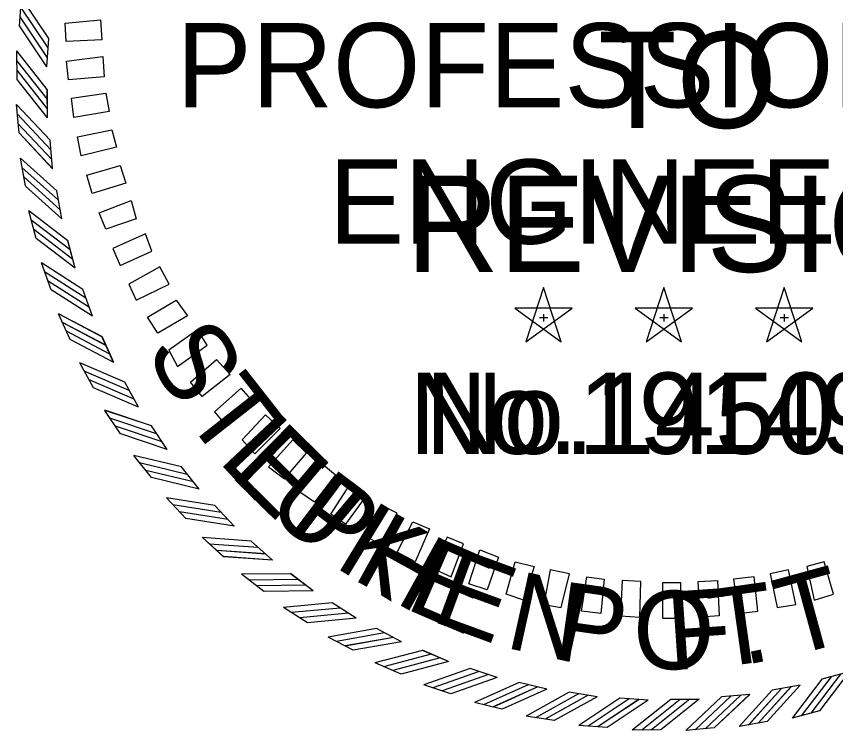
# Model space of a CAD drawing. Extents: x 16 to 1228740, y 11 to 152440.
# Drawn here: x 17.6793 to 17.7882, y 10.8149 to 10.9098 of the extents above; entities that cross this region are included whole.
import ezdxf

# ---------------------------------------------------------------- set-up
doc = ezdxf.new("R2010")
doc.units = 0
for name, color, linetype in [('STAMP_FRED', 7, 'Continuous'), ('STAMP_LUKE', 7, 'Continuous'), ('STAMP_PRELIM', 7, 'Continuous')]:
    doc.layers.add(name, color=color, linetype=linetype)

msp = doc.modelspace()

# ---------------------------------------------------------------- linework, layer by layer
at = {"layer": 'STAMP_FRED'}
for p, q in [((17.6797, 10.90852), (17.67998, 10.91228)), ((17.68332, 10.9031), (17.6836, 10.90687)), ((17.67937, 10.90143), (17.67934, 10.9052)), ((17.68343, 10.89632), (17.68339, 10.9001)), ((17.67963, 10.89432), (17.67928, 10.89808)), ((17.68409, 10.88957), (17.68375, 10.89333)), ((17.68047, 10.88727), (17.67982, 10.89098)), ((17.68531, 10.8829), (17.68466, 10.88662)), ((17.68189, 10.8803), (17.68093, 10.88395)), ((17.68708, 10.87635), (17.68612, 10.88)), ((17.68389, 10.87348), (17.68263, 10.87704)), ((17.68938, 10.86997), (17.68812, 10.87353)), ((17.74935, 10.87379), (17.747, 10.86655)), ((17.7517, 10.86656), (17.74936, 10.8738)), ((17.76534, 10.87379), (17.76299, 10.86655)), ((17.76769, 10.86656), (17.76535, 10.8738)), ((17.78134, 10.87379), (17.77898, 10.86655)), ((17.78369, 10.86656), (17.78134, 10.8738)), ((17.75316, 10.87103), (17.74555, 10.87103)), ((17.74555, 10.87103), (17.7517, 10.86655)), ((17.747, 10.86656), (17.75317, 10.87102)), ((17.76915, 10.87103), (17.76154, 10.87103)), ((17.76154, 10.87103), (17.7677, 10.86655)), ((17.763, 10.86656), (17.76916, 10.87102)), ((17.78514, 10.87103), (17.77753, 10.87103)), ((17.77753, 10.87103), (17.78369, 10.86655)), ((17.77899, 10.86656), (17.78515, 10.87102)), ((17.68644, 10.86685), (17.68489, 10.87029)), ((17.74881, 10.86981), (17.74994, 10.86981)), ((17.74936, 10.87022), (17.74936, 10.86926)), ((17.7648, 10.86981), (17.76593, 10.86981)), ((17.76535, 10.87022), (17.76535, 10.86926)), ((17.78079, 10.86981), (17.78193, 10.86981)), ((17.78134, 10.87022), (17.78134, 10.86926)), ((17.6922, 10.8638), (17.69065, 10.86725)), ((17.68952, 10.86045), (17.6877, 10.86375)), ((17.69552, 10.85789), (17.6937, 10.8612)), ((17.69313, 10.85433), (17.69104, 10.85746)), ((17.69932, 10.85227), (17.69723, 10.85541)), ((17.69723, 10.84852), (17.69489, 10.85148)), ((17.70357, 10.84698), (17.70122, 10.84994)), ((17.7018, 10.84308), (17.69922, 10.84583)), ((17.70824, 10.84207), (17.70566, 10.84482)), ((17.7068, 10.83802), (17.704, 10.84055)), ((17.7133, 10.83755), (17.7105, 10.84009)), ((17.71219, 10.8334), (17.7092, 10.83569)), ((17.71872, 10.83347), (17.71571, 10.83576)), ((17.72445, 10.82985), (17.72127, 10.83189)), ((17.71796, 10.82925), (17.71478, 10.83128)), ((17.73047, 10.82672), (17.72713, 10.82848)), ((17.72404, 10.82558), (17.72071, 10.82734)), ((17.73672, 10.82409), (17.73325, 10.82557)), ((17.73041, 10.82242), (17.72695, 10.82391)), ((17.74317, 10.82199), (17.73958, 10.82318)), ((17.78999, 10.82272), (17.78633, 10.82176)), ((17.73702, 10.81981), (17.73344, 10.821)), ((17.74977, 10.82042), (17.7461, 10.82132)), ((17.78344, 10.82095), (17.77972, 10.82029)), ((17.75647, 10.81941), (17.75274, 10.82)), ((17.77677, 10.81973), (17.77301, 10.81938)), ((17.74382, 10.81774), (17.74016, 10.81864)), ((17.76324, 10.81896), (17.75947, 10.81924)), ((17.77002, 10.81906), (17.76624, 10.81903)), ((17.78603, 10.81753), (17.78239, 10.81657)), ((17.75077, 10.81625), (17.74704, 10.81684)), ((17.75781, 10.81533), (17.75405, 10.81561)), ((17.77202, 10.81526), (17.76826, 10.81492)), ((17.77907, 10.81611), (17.77536, 10.81545)), ((17.76491, 10.815), (17.76114, 10.81497))]:
    msp.add_line(p, q, dxfattribs=at)
for points in [[(17.6836, 10.90686), (17.67997, 10.91229)], [(17.68349, 10.90561), (17.67987, 10.91104)], [(17.68343, 10.9043), (17.6798, 10.90973)], [(17.68333, 10.90309), (17.6797, 10.90852)], [(17.68339, 10.90009), (17.67933, 10.9052)], [(17.68339, 10.89884), (17.67933, 10.90394)], [(17.68343, 10.89753), (17.67937, 10.90263)], [(17.68343, 10.89631), (17.67937, 10.90142)], [(17.68375, 10.89333), (17.67928, 10.89808)], [(17.68385, 10.89208), (17.67938, 10.89683)], [(17.684, 10.89077), (17.67953, 10.89553)], [(17.6841, 10.88956), (17.67963, 10.89432)], [(17.68466, 10.88661), (17.67981, 10.89098)], [(17.68486, 10.88538), (17.68002, 10.88974)], [(17.68512, 10.88409), (17.68028, 10.88846)], [(17.68532, 10.88289), (17.68047, 10.88726)], [(17.68612, 10.88), (17.68093, 10.88395)], [(17.68643, 10.87878), (17.68124, 10.88274)], [(17.68679, 10.87752), (17.6816, 10.88148)], [(17.68709, 10.87635), (17.6819, 10.8803)], [(17.68812, 10.87353), (17.68263, 10.87704)], [(17.68853, 10.87234), (17.68303, 10.87585)], [(17.68899, 10.87112), (17.6835, 10.87463)], [(17.68939, 10.86997), (17.68389, 10.87348)], [(17.69065, 10.86724), (17.68489, 10.87029)], [(17.69116, 10.86609), (17.68539, 10.86914)], [(17.69172, 10.86491), (17.68595, 10.86796)], [(17.69221, 10.8638), (17.68644, 10.86685)], [(17.6937, 10.86119), (17.6877, 10.86375)], [(17.69429, 10.86009), (17.68829, 10.86265)], [(17.69495, 10.85895), (17.68895, 10.86151)], [(17.69553, 10.85789), (17.68953, 10.86045)], [(17.69723, 10.85541), (17.69104, 10.85746)], [(17.69791, 10.85436), (17.69172, 10.85641)], [(17.69866, 10.85328), (17.69247, 10.85534)], [(17.69933, 10.85227), (17.69314, 10.85432)], [(17.70122, 10.84994), (17.69488, 10.85148)], [(17.70199, 10.84895), (17.69566, 10.85049)], [(17.70283, 10.84794), (17.69649, 10.84948)], [(17.70358, 10.84698), (17.69724, 10.84852)], [(17.70566, 10.84482), (17.69921, 10.84583)], [(17.70651, 10.84389), (17.70006, 10.8449)], [(17.70743, 10.84296), (17.70098, 10.84397)], [(17.70825, 10.84207), (17.7018, 10.84307)], [(17.7105, 10.84008), (17.70399, 10.84055)], [(17.71142, 10.83923), (17.70492, 10.8397)], [(17.71241, 10.83837), (17.70591, 10.83885)], [(17.71331, 10.83755), (17.7068, 10.83802)], [(17.71572, 10.83576), (17.70919, 10.83569)], [(17.71671, 10.83499), (17.71019, 10.83492)], [(17.71777, 10.83422), (17.71124, 10.83415)], [(17.71872, 10.83347), (17.7122, 10.8334)], [(17.72127, 10.83188), (17.71478, 10.83128)], [(17.72232, 10.8312), (17.71583, 10.83059)], [(17.72344, 10.83051), (17.71695, 10.82991)], [(17.72446, 10.82985), (17.71796, 10.82925)], [(17.72713, 10.82848), (17.72071, 10.82734)], [(17.72823, 10.82788), (17.72181, 10.82674)], [(17.72941, 10.82729), (17.72298, 10.82615)], [(17.73047, 10.82672), (17.72405, 10.82558)], [(17.73325, 10.82557), (17.72694, 10.8239)], [(17.7344, 10.82507), (17.72809, 10.8234)], [(17.73561, 10.82458), (17.72931, 10.82291)], [(17.73673, 10.82409), (17.73042, 10.82242)], [(17.73959, 10.82318), (17.73344, 10.821)], [(17.74077, 10.82277), (17.73463, 10.82059)], [(17.74203, 10.82238), (17.73588, 10.8202)], [(17.74317, 10.82199), (17.73703, 10.81981)], [(17.78634, 10.82175), (17.78239, 10.81657)], [(17.78756, 10.82206), (17.7836, 10.81687)], [(17.78882, 10.82242), (17.78486, 10.81723)], [(17.78999, 10.82272), (17.78604, 10.81753)], [(17.7461, 10.82131), (17.74015, 10.81863)], [(17.74732, 10.82101), (17.74137, 10.81833)], [(17.7486, 10.82072), (17.74265, 10.81804)], [(17.78225, 10.82075), (17.77788, 10.81591)], [(17.78345, 10.82095), (17.77908, 10.81611)], [(17.74977, 10.82043), (17.74383, 10.81775)], [(17.75274, 10.82), (17.74704, 10.81683)], [(17.75398, 10.81979), (17.74828, 10.81663)], [(17.75528, 10.81961), (17.74958, 10.81645)], [(17.77556, 10.81963), (17.77081, 10.81517)], [(17.77677, 10.81973), (17.77202, 10.81527)], [(17.77972, 10.82029), (17.77536, 10.81545)], [(17.78096, 10.8205), (17.77659, 10.81565)], [(17.75648, 10.81942), (17.75077, 10.81625)], [(17.75948, 10.81923), (17.75405, 10.81561)], [(17.76073, 10.81913), (17.7553, 10.81551)], [(17.76204, 10.81906), (17.75661, 10.81544)], [(17.76324, 10.81896), (17.75782, 10.81534)], [(17.76625, 10.81903), (17.76114, 10.81497)], [(17.7675, 10.81903), (17.7624, 10.81497)], [(17.76881, 10.81907), (17.76371, 10.81501)], [(17.77003, 10.81907), (17.76492, 10.81501)], [(17.77301, 10.81938), (17.76826, 10.81491)], [(17.77426, 10.81948), (17.76951, 10.81502)]]:
    msp.add_lwpolyline(points, dxfattribs=at)
at = {"layer": 'STAMP_LUKE'}
for p, q in [((17.6797, 10.90852), (17.67998, 10.91228)), ((17.68332, 10.9031), (17.6836, 10.90687)), ((17.67937, 10.90143), (17.67934, 10.9052)), ((17.68343, 10.89632), (17.6834, 10.9001)), ((17.67963, 10.89432), (17.67928, 10.89808)), ((17.6841, 10.88957), (17.68375, 10.89333)), ((17.68047, 10.88727), (17.67982, 10.89098)), ((17.68532, 10.8829), (17.68466, 10.88662)), ((17.68189, 10.88031), (17.68094, 10.88395)), ((17.68708, 10.87635), (17.68612, 10.88001)), ((17.68389, 10.87348), (17.68263, 10.87704)), ((17.68938, 10.86997), (17.68812, 10.87353)), ((17.74935, 10.87379), (17.74699, 10.86655)), ((17.7517, 10.86656), (17.74936, 10.8738)), ((17.76534, 10.87379), (17.76299, 10.86655)), ((17.76769, 10.86656), (17.76535, 10.8738)), ((17.78133, 10.87379), (17.77898, 10.86655)), ((17.78368, 10.86656), (17.78134, 10.8738)), ((17.75316, 10.87103), (17.74554, 10.87103)), ((17.74555, 10.87103), (17.7517, 10.86655)), ((17.747, 10.86656), (17.75316, 10.87103)), ((17.76915, 10.87103), (17.76154, 10.87103)), ((17.76154, 10.87103), (17.76769, 10.86655)), ((17.76299, 10.86656), (17.76916, 10.87103)), ((17.78514, 10.87103), (17.77753, 10.87103)), ((17.77753, 10.87103), (17.78369, 10.86655)), ((17.77898, 10.86656), (17.78515, 10.87103)), ((17.68644, 10.86685), (17.68489, 10.87029)), ((17.74881, 10.86981), (17.74994, 10.86981)), ((17.74936, 10.87022), (17.74936, 10.86926)), ((17.7648, 10.86981), (17.76593, 10.86981)), ((17.76535, 10.87022), (17.76535, 10.86926)), ((17.78079, 10.86981), (17.78192, 10.86981)), ((17.78134, 10.87022), (17.78134, 10.86926)), ((17.69221, 10.8638), (17.69066, 10.86725)), ((17.68953, 10.86045), (17.6877, 10.86375)), ((17.69553, 10.85789), (17.6937, 10.8612)), ((17.69313, 10.85433), (17.69104, 10.85746)), ((17.69932, 10.85227), (17.69723, 10.85542)), ((17.69723, 10.84852), (17.69489, 10.85148)), ((17.70357, 10.84699), (17.70122, 10.84995)), ((17.7018, 10.84308), (17.69922, 10.84583)), ((17.70824, 10.84207), (17.70566, 10.84483)), ((17.7068, 10.83803), (17.704, 10.84055)), ((17.7133, 10.83755), (17.7105, 10.84009)), ((17.71219, 10.83341), (17.7092, 10.83569)), ((17.71872, 10.83347), (17.71572, 10.83577)), ((17.72445, 10.82985), (17.72127, 10.83189)), ((17.71796, 10.82925), (17.71478, 10.83128)), ((17.73047, 10.82672), (17.72713, 10.82849)), ((17.72404, 10.82558), (17.72071, 10.82734)), ((17.73672, 10.82409), (17.73324, 10.82558)), ((17.73041, 10.82243), (17.72695, 10.82391)), ((17.74317, 10.82199), (17.73958, 10.82318)), ((17.78999, 10.82272), (17.78633, 10.82176)), ((17.73702, 10.81981), (17.73344, 10.821)), ((17.74977, 10.82043), (17.7461, 10.82132)), ((17.78344, 10.82095), (17.77972, 10.8203)), ((17.75647, 10.81941), (17.75274, 10.82)), ((17.77677, 10.81973), (17.77301, 10.81938)), ((17.74382, 10.81775), (17.74016, 10.81864)), ((17.76324, 10.81896), (17.75947, 10.81924)), ((17.77002, 10.81907), (17.76624, 10.81903)), ((17.78603, 10.81753), (17.78239, 10.81657)), ((17.75077, 10.81625), (17.74704, 10.81684)), ((17.75781, 10.81534), (17.75405, 10.81561)), ((17.77201, 10.81526), (17.76826, 10.81492)), ((17.77907, 10.81611), (17.77536, 10.81545)), ((17.76491, 10.81501), (17.76114, 10.81497))]:
    msp.add_line(p, q, dxfattribs=at)
for points in [[(17.6836, 10.90686), (17.67998, 10.91229)], [(17.68349, 10.90561), (17.67987, 10.91104)], [(17.68343, 10.9043), (17.6798, 10.90973)], [(17.68333, 10.90309), (17.6797, 10.90852)], [(17.68339, 10.90009), (17.67933, 10.9052)], [(17.68339, 10.89884), (17.67933, 10.90394)], [(17.68343, 10.89753), (17.67937, 10.90263)], [(17.68343, 10.89631), (17.67937, 10.90142)], [(17.68375, 10.89333), (17.67928, 10.89808)], [(17.68385, 10.89208), (17.67938, 10.89683)], [(17.684, 10.89077), (17.67953, 10.89553)], [(17.6841, 10.88957), (17.67963, 10.89432)], [(17.68466, 10.88661), (17.67981, 10.89098)], [(17.68486, 10.88538), (17.68002, 10.88974)], [(17.68512, 10.88409), (17.68028, 10.88846)], [(17.68532, 10.88289), (17.68048, 10.88726)], [(17.68612, 10.88), (17.68093, 10.88395)], [(17.68643, 10.87878), (17.68124, 10.88274)], [(17.68679, 10.87752), (17.6816, 10.88148)], [(17.68709, 10.87635), (17.6819, 10.8803)], [(17.68812, 10.87353), (17.68263, 10.87704)], [(17.68853, 10.87234), (17.68303, 10.87585)], [(17.689, 10.87112), (17.6835, 10.87463)], [(17.68939, 10.86997), (17.68389, 10.87348)], [(17.69065, 10.86725), (17.68489, 10.87029)], [(17.69116, 10.8661), (17.68539, 10.86914)], [(17.69172, 10.86491), (17.68595, 10.86796)], [(17.69221, 10.8638), (17.68644, 10.86685)], [(17.6937, 10.86119), (17.6877, 10.86375)], [(17.69429, 10.86009), (17.68829, 10.86265)], [(17.69495, 10.85896), (17.68895, 10.86152)], [(17.69553, 10.85789), (17.68953, 10.86045)], [(17.69723, 10.85541), (17.69104, 10.85747)], [(17.69791, 10.85436), (17.69172, 10.85641)], [(17.69866, 10.85329), (17.69247, 10.85534)], [(17.69933, 10.85227), (17.69314, 10.85433)], [(17.70122, 10.84994), (17.69488, 10.85148)], [(17.702, 10.84895), (17.69566, 10.85049)], [(17.70283, 10.84794), (17.69649, 10.84948)], [(17.70358, 10.84698), (17.69724, 10.84852)], [(17.70566, 10.84482), (17.69921, 10.84583)], [(17.70651, 10.8439), (17.70006, 10.8449)], [(17.70743, 10.84296), (17.70098, 10.84397)], [(17.70825, 10.84207), (17.7018, 10.84308)], [(17.7105, 10.84008), (17.70399, 10.84055)], [(17.71142, 10.83923), (17.70492, 10.8397)], [(17.71242, 10.83838), (17.70591, 10.83885)], [(17.71331, 10.83755), (17.7068, 10.83803)], [(17.71572, 10.83576), (17.70919, 10.83569)], [(17.71671, 10.83499), (17.71019, 10.83492)], [(17.71777, 10.83422), (17.71124, 10.83415)], [(17.71872, 10.83347), (17.7122, 10.83341)], [(17.72127, 10.83188), (17.71478, 10.83128)], [(17.72232, 10.8312), (17.71583, 10.83059)], [(17.72344, 10.83052), (17.71695, 10.82991)], [(17.72446, 10.82985), (17.71796, 10.82925)], [(17.72713, 10.82848), (17.72071, 10.82734)], [(17.72823, 10.82788), (17.72181, 10.82674)], [(17.72941, 10.8273), (17.72298, 10.82616)], [(17.73047, 10.82672), (17.72405, 10.82558)], [(17.73325, 10.82557), (17.72694, 10.82391)], [(17.7344, 10.82507), (17.72809, 10.8234)], [(17.73561, 10.82458), (17.72931, 10.82291)], [(17.73672, 10.82409), (17.73042, 10.82243)], [(17.73959, 10.82318), (17.73344, 10.821)], [(17.74077, 10.82277), (17.73463, 10.82059)], [(17.74202, 10.82238), (17.73588, 10.8202)], [(17.74317, 10.82199), (17.73702, 10.81981)], [(17.78634, 10.82176), (17.78238, 10.81657)], [(17.78756, 10.82206), (17.7836, 10.81688)], [(17.78881, 10.82243), (17.78486, 10.81724)], [(17.78999, 10.82272), (17.78604, 10.81754)], [(17.7461, 10.82132), (17.74015, 10.81864)], [(17.74732, 10.82101), (17.74137, 10.81833)], [(17.7486, 10.82073), (17.74265, 10.81805)], [(17.78225, 10.82076), (17.77788, 10.81591)], [(17.78344, 10.82096), (17.77907, 10.81611)], [(17.74977, 10.82043), (17.74383, 10.81775)], [(17.75274, 10.82), (17.74704, 10.81684)], [(17.75398, 10.81979), (17.74828, 10.81663)], [(17.75528, 10.81962), (17.74958, 10.81645)], [(17.77556, 10.81964), (17.77081, 10.81517)], [(17.77677, 10.81974), (17.77202, 10.81527)], [(17.77972, 10.82029), (17.77535, 10.81545)], [(17.78096, 10.8205), (17.77659, 10.81566)], [(17.75648, 10.81942), (17.75077, 10.81625)], [(17.75947, 10.81923), (17.75405, 10.81561)], [(17.76073, 10.81913), (17.7553, 10.81551)], [(17.76203, 10.81906), (17.75661, 10.81544)], [(17.76324, 10.81896), (17.75782, 10.81534)], [(17.76625, 10.81903), (17.76114, 10.81497)], [(17.7675, 10.81903), (17.7624, 10.81497)], [(17.76881, 10.81907), (17.7637, 10.81501)], [(17.77002, 10.81907), (17.76492, 10.81501)], [(17.77301, 10.81938), (17.76826, 10.81492)], [(17.77426, 10.81949), (17.76951, 10.81502)]]:
    msp.add_lwpolyline(points, dxfattribs=at)
at = {"layer": 'STAMP_PRELIM'}
for p, q in [((17.68578, 10.90891), (17.69046, 10.90935)), ((17.6859, 10.90647), (17.68578, 10.90891)), ((17.69046, 10.90935), (17.69065, 10.90666)), ((17.69065, 10.90666), (17.6859, 10.90647)), ((17.68596, 10.90385), (17.69078, 10.90447)), ((17.69078, 10.90447), (17.69096, 10.90178)), ((17.68621, 10.90135), (17.68596, 10.90385)), ((17.69096, 10.90178), (17.68621, 10.90135)), ((17.68659, 10.89891), (17.69115, 10.8996)), ((17.69115, 10.8996), (17.69159, 10.89716)), ((17.6869, 10.89635), (17.68659, 10.89891)), ((17.69159, 10.89716), (17.6869, 10.89635)), ((17.6874, 10.89378), (17.69196, 10.89472)), ((17.69196, 10.89472), (17.69259, 10.89241)), ((17.6879, 10.89128), (17.6874, 10.89378)), ((17.69259, 10.89241), (17.6879, 10.89128)), ((17.68865, 10.88872), (17.69309, 10.88997)), ((17.69309, 10.88997), (17.69384, 10.88766)), ((17.68934, 10.88628), (17.68865, 10.88872)), ((17.69384, 10.88766), (17.68934, 10.88628)), ((17.69028, 10.88372), (17.69453, 10.88535)), ((17.69453, 10.88535), (17.69521, 10.88291)), ((17.69115, 10.88153), (17.69028, 10.88372)), ((17.69521, 10.88291), (17.69115, 10.88153)), ((17.69646, 10.88091), (17.69209, 10.87897)), ((17.69728, 10.8786), (17.69646, 10.88091)), ((17.69209, 10.87897), (17.69309, 10.87672)), ((17.69309, 10.87672), (17.69728, 10.8786)), ((17.69834, 10.87653), (17.69421, 10.87422)), ((17.69959, 10.87422), (17.69834, 10.87653)), ((17.69421, 10.87422), (17.69521, 10.8721)), ((17.69521, 10.8721), (17.69959, 10.87422)), ((17.69671, 10.86985), (17.70053, 10.8721)), ((17.70053, 10.8721), (17.70203, 10.87003)), ((17.69809, 10.86772), (17.69671, 10.86985)), ((17.70203, 10.87003), (17.69809, 10.86772)), ((17.70334, 10.86816), (17.69953, 10.86547)), ((17.70465, 10.8661), (17.70334, 10.86816)), ((17.69953, 10.86547), (17.70071, 10.86328)), ((17.70071, 10.86328), (17.70465, 10.8661)), ((17.7024, 10.86122), (17.7059, 10.86422)), ((17.7059, 10.86422), (17.70771, 10.86222)), ((17.70771, 10.86222), (17.70396, 10.85928)), ((17.70396, 10.85928), (17.7024, 10.86122)), ((17.70915, 10.86041), (17.70559, 10.85728)), ((17.71078, 10.85853), (17.70915, 10.86041)), ((17.70721, 10.85535), (17.71078, 10.85853)), ((17.70559, 10.85728), (17.70721, 10.85535)), ((17.70928, 10.85353), (17.7124, 10.85685)), ((17.7124, 10.85685), (17.71434, 10.85503)), ((17.71434, 10.85503), (17.71096, 10.85166)), ((17.71096, 10.85166), (17.70928, 10.85353)), ((17.71603, 10.85353), (17.71278, 10.84997)), ((17.71784, 10.85178), (17.71603, 10.85353)), ((17.7149, 10.84835), (17.71784, 10.85178)), ((17.71696, 10.8466), (17.71978, 10.85047)), ((17.71978, 10.85047), (17.72171, 10.84891)), ((17.71278, 10.84997), (17.7149, 10.84835)), ((17.72171, 10.84891), (17.7189, 10.84528)), ((17.72109, 10.84366), (17.72365, 10.84766)), ((17.72365, 10.84766), (17.72584, 10.84622)), ((17.7189, 10.84528), (17.71696, 10.8466)), ((17.72584, 10.84622), (17.72303, 10.84235)), ((17.72771, 10.84485), (17.72559, 10.84078)), ((17.7299, 10.84378), (17.72771, 10.84485)), ((17.72303, 10.84235), (17.72109, 10.84366)), ((17.72759, 10.83972), (17.7299, 10.84378)), ((17.7299, 10.8386), (17.73196, 10.84266)), ((17.73196, 10.84266), (17.73421, 10.84172)), ((17.73421, 10.84172), (17.73228, 10.83735)), ((17.72559, 10.84078), (17.72759, 10.83972)), ((17.73653, 10.8406), (17.73465, 10.83647)), ((17.73871, 10.83972), (17.73653, 10.8406)), ((17.73709, 10.83535), (17.73871, 10.83972)), ((17.73228, 10.83735), (17.7299, 10.8386)), ((17.7394, 10.83441), (17.7409, 10.83891)), ((17.7409, 10.83891), (17.74334, 10.83797)), ((17.74334, 10.83797), (17.74184, 10.8336)), ((17.7444, 10.83303), (17.74559, 10.83735)), ((17.74559, 10.83735), (17.74809, 10.83672)), ((17.78665, 10.83735), (17.78433, 10.83672)), ((17.7879, 10.83303), (17.78665, 10.83735)), ((17.73465, 10.83647), (17.73709, 10.83535)), ((17.74809, 10.83672), (17.74671, 10.83222)), ((17.75021, 10.83628), (17.7494, 10.83166)), ((17.75278, 10.83572), (17.75021, 10.83628)), ((17.7819, 10.83628), (17.77946, 10.83572)), ((17.7829, 10.83166), (17.7819, 10.83628)), ((17.78433, 10.83672), (17.78533, 10.83222)), ((17.75171, 10.83128), (17.75278, 10.83572)), ((17.7544, 10.83078), (17.75509, 10.83535)), ((17.75509, 10.83535), (17.7574, 10.83503)), ((17.7574, 10.83503), (17.75696, 10.83047)), ((17.75978, 10.83485), (17.75959, 10.83016)), ((17.76228, 10.83472), (17.75978, 10.83485)), ((17.7699, 10.83472), (17.77246, 10.83485)), ((17.77246, 10.83485), (17.77271, 10.83016)), ((17.77734, 10.83535), (17.77459, 10.83503)), ((17.77459, 10.83503), (17.77528, 10.83047)), ((17.77784, 10.83078), (17.77734, 10.83535)), ((17.77946, 10.83572), (17.7804, 10.83128)), ((17.74184, 10.8336), (17.7394, 10.83441)), ((17.76215, 10.82997), (17.76228, 10.83472)), ((17.76515, 10.83453), (17.76515, 10.82985)), ((17.76759, 10.83453), (17.76515, 10.83453)), ((17.76759, 10.82985), (17.76759, 10.83453)), ((17.77015, 10.82997), (17.7699, 10.83472)), ((17.74671, 10.83222), (17.7444, 10.83303)), ((17.78533, 10.83222), (17.7879, 10.83303)), ((17.7494, 10.83166), (17.75171, 10.83128)), ((17.7804, 10.83128), (17.7829, 10.83166)), ((17.75696, 10.83047), (17.7544, 10.83078)), ((17.77528, 10.83047), (17.77784, 10.83078)), ((17.75959, 10.83016), (17.76215, 10.82997)), ((17.76515, 10.82985), (17.76759, 10.82985)), ((17.77271, 10.83016), (17.77015, 10.82997))]:
    msp.add_line(p, q, dxfattribs=at)

# ---------------------------------------------------------------- texts
at = {"layer": 'STAMP_FRED'}
for s, height, p in [('PROFESSIONAL', 0.0111938, (17.70056, 10.89771)), ('ENGINEER', 0.011194, (17.72082, 10.87959)), ('No.14501', 0.010794, (17.73362, 10.85168))]:
    msp.add_text(s, height=height, dxfattribs=at).set_placement(p)
for s, rotation, p in [('S', 300.7985, (17.69626, 10.86535)), ('T', 308.0945, (17.70135, 10.85681)), ('E', 315.3905, (17.70747, 10.849)), ('P', 323.0513, (17.71492, 10.8417)), ('H', 331.0769, (17.7237, 10.83519)), ('E', 339.8321, (17.7342, 10.82956)), ('N', 347.4929, (17.744, 10.82599)), ('F', 3.9089, (17.76608, 10.82291)), ('.', 11.205, (17.77599, 10.82359))]:
    msp.add_text(s, height=0.01042, rotation=rotation, dxfattribs=at).set_placement(p)
at = {"layer": 'STAMP_LUKE'}
for s, height, p in [('PROFESSIONAL', 0.0111936, (17.70056, 10.89771)), ('ENGINEER', 0.011194, (17.72082, 10.87959)), ('No.19149', 0.010794, (17.73148, 10.85168)), ('O', 0.01042, (17.76125, 10.82307))]:
    msp.add_text(s, height=height, dxfattribs=at).set_placement(p)
for s, rotation, p in [('L', 313.3055, (17.70596, 10.85079)), ('U', 319.8719, (17.71209, 10.84429)), ('K', 328.6272, (17.72135, 10.83679)), ('E', 336.6528, (17.73074, 10.83122)), ('T', 15.3216, (17.782, 10.82466)), ('P', 351.9744, (17.75042, 10.82446)), ('T', 8.0256, (17.77217, 10.82321))]:
    msp.add_text(s, height=0.01042, rotation=rotation, dxfattribs=at).set_placement(p)
at = {"layer": 'STAMP_PRELIM'}
for s, p in [('TO', (17.75659, 10.89497)), ('REVISION', (17.73109, 10.87585))]:
    msp.add_text(s, height=0.012794, dxfattribs=at).set_placement(p)

doc.saveas('drawing.dxf')
